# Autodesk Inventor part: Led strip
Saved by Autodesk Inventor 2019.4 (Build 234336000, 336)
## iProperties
Created: 2019-12
Part Number: Led strip
Material: Generic
Document SubType Name: Modeling
Designer: Administrator
Density: 1 g/cm^3
Appearance: Default
Title: Led strip v1
Author: Administrator
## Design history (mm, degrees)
feature "Body1"
body "Solid1"
